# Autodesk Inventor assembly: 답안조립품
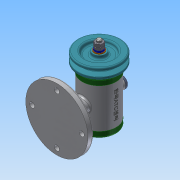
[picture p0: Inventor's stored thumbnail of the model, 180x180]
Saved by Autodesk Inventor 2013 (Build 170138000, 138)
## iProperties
Created: 2018-12
Part Number: 답안조립품
Document SubType Name: Assembly
Designer: Administrator
Author: Administrator
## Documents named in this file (15)
- C:\Users\Administrator\Desktop\481207V1041\OldVersions\답안조립품.iam
- C:\Users\Administrator\Desktop\481207V1041\본체.ipt
- C:\Users\Administrator\Desktop\481207V1041\베어링 15 x 32 x 9.ipt
- C:\Users\Administrator\Desktop\481207V1041\앞커버.ipt
- C:\Users\Administrator\Desktop\481207V1041\뒤커버.ipt
- C:\Users\Administrator\Desktop\481207V1041\축.ipt
- C:\Users\Administrator\Desktop\481207V1041\오일 실 15 25 7.ipt
- C:\Users\Administrator\Desktop\481207V1041\볼트 M4 x 12.ipt
- C:\Users\Administrator\Desktop\481207V1041\키 3 x 3 x 12.ipt
- C:\Users\Administrator\Desktop\481207V1041\V벨트풀리.ipt
- C:\Users\Administrator\Desktop\481207V1041\와셔 8x17.ipt
- C:\Users\Administrator\Desktop\481207V1041\스프링와셔 8.ipt
- C:\Users\Administrator\Desktop\481207V1041\너트 M8.ipt
- 너트 M8.ipt
- C:\Users\Administrator\Desktop\481207V1041\고무캡.ipt
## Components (2 placed, 2 different names)
1. V벨트풀리:1
2. 고무캡:1
